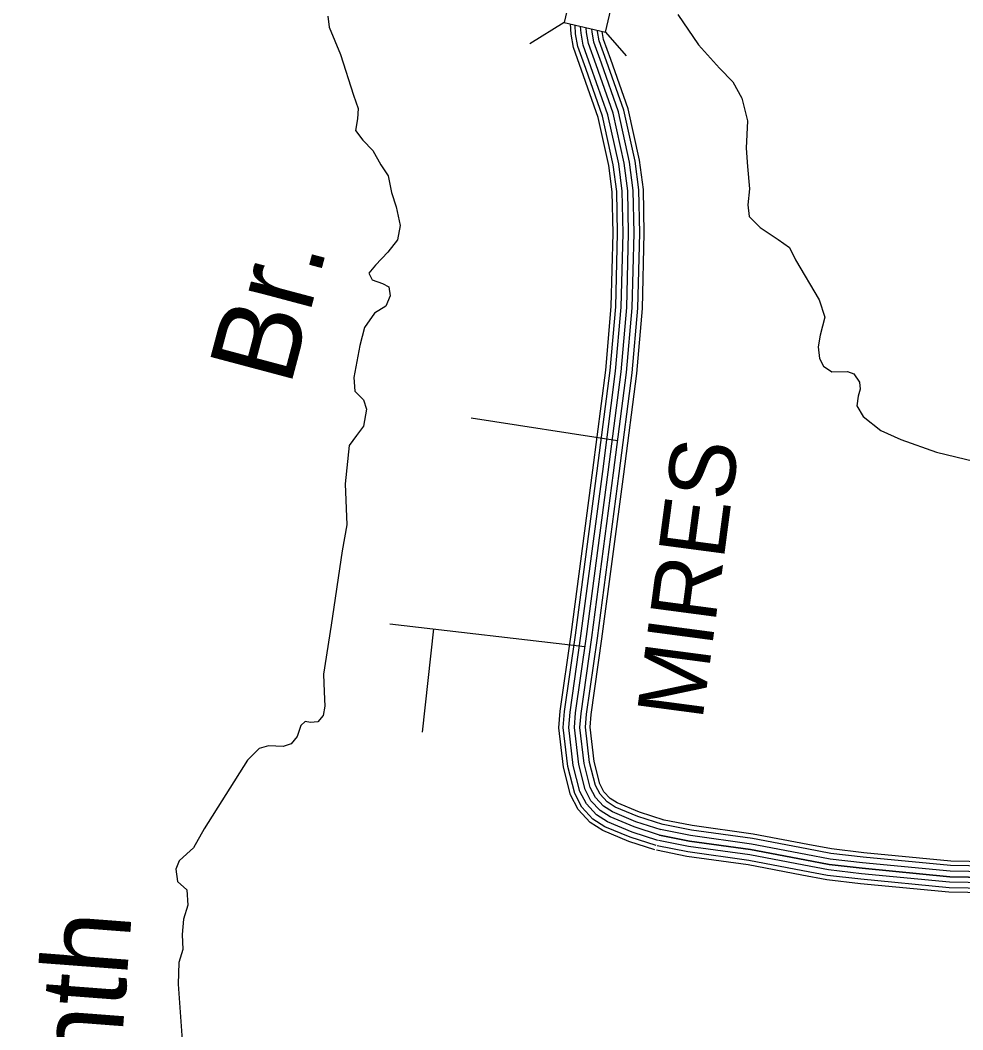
# Model space of a CAD drawing. Extents: x 1788175 to 1969470, y 584502 to 738744.
# Drawn here: x 1823466 to 1828747, y 641514 to 647171 of the extents above; entities that cross this region are included whole.
import ezdxf

# ---------------------------------------------------------------- set-up
doc = ezdxf.new("R2010")
doc.units = 0
for name, color, linetype in [('DESIGN - DRAINAGE - Bridges and Cross Drains Size Text', 7, 'Continuous'), ('DESIGN - ROW - Right-of-Way and Easement Labels', 7, 'Continuous'), ('DESIGN - TRANSPORTATION - Text', 7, 'Continuous'), ('SURVEY - DRAINAGE - Storm Sewer', 7, 'Continuous'), ('SURVEY - TRANSPORTATION - Roads', 7, 'Continuous')]:
    doc.layers.add(name, color=color, linetype=linetype)

msp = doc.modelspace()

# ---------------------------------------------------------------- linework, layer by layer
at = {"layer": 'DESIGN - TRANSPORTATION - Text'}
for points in [[(1825190.2, 647193.3), (1825196.9, 647131.5), (1825260.8, 646978.4), (1825333.6, 646751.5), (1825360.5, 646675.9), (1825355.3, 646617.9), (1825344.1, 646553.7), (1825386.7, 646498.4), (1825441.4, 646441.1), (1825486.4, 646359.8), (1825527.1, 646298.4), (1825546.3, 646204.7), (1825573.2, 646125.1), (1825594.5, 646021.4), (1825579.6, 645941.2), (1825526.6, 645870.5), (1825457.6, 645797.6), (1825420.2, 645753.1), (1825438.7, 645715.4), (1825496.8, 645696.2), (1825531, 645676.7), (1825539.7, 645626.8), (1825514.4, 645568.5), (1825451, 645529.6), (1825396.1, 645448.9), (1825369.5, 645348.5), (1825335.8, 645168.1), (1825340.8, 645092.2), (1825389.3, 645042.9), (1825406, 644991.2), (1825389.2, 644897), (1825349.9, 644844.5), (1825308.7, 644787.9), (1825287.5, 644573.7), (1825296.4, 644343.9), (1825270.3, 644197.6), (1825207.7, 643780.9), (1825165.3, 643506.4), (1825168.5, 643408.5), (1825173.6, 643326.6), (1825164.3, 643274.5), (1825134.7, 643240.1), (1825092.9, 643235.5), (1825062.8, 643241.1), (1825039.2, 643218.7), (1825018, 643156.5), (1824984.6, 643116), (1824938.8, 643101.4), (1824856.9, 643104.3), (1824805.2, 643089.5), (1824740.1, 643024.7), (1824497.4, 642639.4), (1824436.8, 642532.6), (1824399.3, 642500.1), (1824357.8, 642461.6), (1824338.5, 642413.3), (1824347.3, 642345.4), (1824399.9, 642298.2), (1824405, 642212.3), (1824382, 642134), (1824373.1, 642047.9), (1824378.2, 641964), (1824355.1, 641891.7), (1824350.7, 641769.7), (1824379.7, 641378.3)], [(1827151.1, 647202.7), (1827267.1, 647032.3), (1827384.6, 646902), (1827459.5, 646825.1), (1827508.6, 646733.8), (1827540.2, 646606.3), (1827534.1, 646454.3), (1827541.4, 646350.4), (1827553, 646226.6), (1827542.2, 646136.5), (1827551, 646070.7), (1827611.7, 646009.5), (1827712.4, 645943), (1827776.9, 645897.9), (1827809.7, 645828.4), (1827942.4, 645604.3), (1827973.6, 645506.8), (1827948.9, 645406.5), (1827937.8, 645340.3), (1827944.6, 645274.5), (1827967.1, 645232.8), (1828013.4, 645201.4), (1828101.3, 645202.7), (1828137.4, 645189.2), (1828167.9, 645143.6), (1828172.4, 645103.7), (1828160.9, 645063.5), (1828153.6, 645009.5), (1828188.4, 644950), (1828287.2, 644871.4), (1828399.7, 644821), (1828600.3, 644749.8)], [(1828600.3, 644749.8), (1828916.8, 644674.2)]]:
    msp.add_lwpolyline(points, dxfattribs=at)
at = {"layer": 'SURVEY - DRAINAGE - Storm Sewer'}
for p, q in [((1826514, 647158.1), (1826320.9, 647038.6)), ((1826745.3, 647103.7), (1826861.4, 646970.5))]:
    msp.add_line(p, q, dxfattribs=at)
msp.add_lwpolyline([(1826745.3, 647103.7), (1826799.7, 647335), (1826568.5, 647389.4), (1826514, 647158.1)], close=True, dxfattribs=at)
at = {"layer": 'SURVEY - TRANSPORTATION - Roads'}
for points in [[(1827021.4, 642522.5), (1826875.6, 642569.6), (1826731.2, 642629.8), (1826658.8, 642675), (1826592.4, 642747.5), (1826549.8, 642830), (1826510.2, 642984.6), (1826483.9, 643206.6), (1826491.8, 643299.9), (1826552.5, 643728.6), (1826674.5, 644649.4), (1826746.9, 645210.3), (1826777.9, 645566.2), (1826788.5, 645977.5), (1826783.6, 646208.7), (1826764.7, 646355.9), (1826705.2, 646626), (1826611.8, 646891.1), (1826565.8, 647017.3), (1826552.8, 647091.9), (1826549.9, 647149.7)], [(1827029, 642546), (1826884.1, 642592.8), (1826742.6, 642651.8), (1826674.8, 642694.2), (1826612.8, 642761.8), (1826573, 642838.9), (1826534.6, 642989.1), (1826508.7, 643207), (1826516.3, 643297.1), (1826577, 643725.3), (1826699, 644646.2), (1826771.5, 645207.7), (1826802.6, 645564.8), (1826813.2, 645977.4), (1826808.2, 646210.5), (1826789.1, 646360.2), (1826729, 646632.8), (1826635, 646899.5), (1826589.8, 647023.7), (1826577.5, 647094.6), (1826574.9, 647143.8)], [(1827038.5, 642575.5), (1826894.9, 642621.9), (1826756.9, 642679.4), (1826694.8, 642718.2), (1826638.5, 642779.7), (1826602.2, 642850), (1826565.1, 642994.8), (1826539.9, 643207.6), (1826547.1, 643293.6), (1826607.7, 643721.1), (1826729.7, 644642.2), (1826802.3, 645204.3), (1826833.6, 645563), (1826844.2, 645977.4), (1826839.2, 646212.8), (1826819.6, 646365.5), (1826758.9, 646641.3), (1826664.2, 646909.9), (1826619.9, 647031.7), (1826608.3, 647098.1), (1826606.4, 647136.4)], [(1827048, 642605), (1826905.6, 642651), (1826771.1, 642707.1), (1826714.8, 642742.3), (1826664.1, 642797.5), (1826631.4, 642861.1), (1826595.6, 643000.5), (1826571, 643208.1), (1826578, 643290.2), (1826638.4, 643716.8), (1826760.5, 644638.2), (1826833.2, 645201), (1826864.5, 645561.3), (1826875.2, 645977.3), (1826870.2, 646215.1), (1826850.2, 646370.8), (1826788.7, 646649.8), (1826693.4, 646920.4), (1826650, 647039.7), (1826639.2, 647101.6), (1826637.8, 647129)], [(1827048, 642605), (1826905.6, 642651), (1826771.1, 642707.1), (1826714.8, 642742.3), (1826664.1, 642797.5), (1826631.4, 642861.1), (1826595.6, 643000.5), (1826571, 643208.1), (1826578, 643290.2), (1826638.4, 643716.8), (1826760.5, 644638.2), (1826833.2, 645201), (1826864.5, 645561.3), (1826875.2, 645977.3), (1826870.2, 646215.1), (1826850.2, 646370.8), (1826788.7, 646649.8), (1826693.4, 646920.4), (1826650, 647039.7), (1826639.2, 647101.6), (1826637.8, 647129)], [(1827057.6, 642634.5), (1826916.4, 642680.1), (1826785.4, 642734.7), (1826734.8, 642766.3), (1826689.8, 642815.4), (1826660.5, 642872.2), (1826626.2, 643006.2), (1826602.2, 643208.6), (1826608.8, 643286.7), (1826669.1, 643712.6), (1826791.2, 644634.2), (1826864, 645197.7), (1826895.5, 645559.6), (1826906.2, 645977.2), (1826901.1, 646217.4), (1826880.8, 646376.1), (1826818.6, 646658.3), (1826722.6, 646930.8), (1826680, 647047.8), (1826670, 647105), (1826669.2, 647121.6)], [(1827067.1, 642664), (1826927.1, 642709.2), (1826799.7, 642762.3), (1826754.8, 642790.4), (1826715.4, 642833.3), (1826689.7, 642883.3), (1826656.7, 643011.9), (1826633.3, 643209.1), (1826639.6, 643283.2), (1826699.8, 643708.4), (1826821.9, 644630.2), (1826894.8, 645194.3), (1826926.5, 645557.8), (1826937.2, 645977.1), (1826932.1, 646219.7), (1826911.3, 646381.4), (1826848.5, 646666.9), (1826751.8, 646941.3), (1826710.1, 647055.8), (1826700.9, 647108.5), (1826700.6, 647114.2)], [(1827075, 642688.4), (1826936.1, 642733.3), (1826811.5, 642785.3), (1826771.4, 642810.3), (1826736.7, 642848.2), (1826713.9, 642892.5), (1826682.1, 643016.6), (1826659.2, 643209.6), (1826665.2, 643280.3), (1826725.3, 643704.9), (1826847.4, 644626.8), (1826920.4, 645191.6), (1826952.1, 645556.4), (1826962.9, 645977.1), (1826957.8, 646221.7), (1826936.7, 646385.8), (1826873.2, 646673.9), (1826776, 646950), (1826735, 647062.5), (1826727.1, 647108)], [(1826812.8, 644813.8), (1825993.3, 644941.4)], [(1825537.6, 643788.6), (1826630.5, 643661.2)], [(1825781, 643760.3), (1825718.9, 643181.2)], [(1831873.7, 641823.1), (1831191.7, 641894.4), (1831067.9, 641913.6), (1831035.9, 641923.8), (1831007, 641939.4), (1830897.7, 642010.1), (1830796.9, 642062.1), (1830711.9, 642092.6), (1830406.4, 642191.3), (1829947.7, 642309.9), (1829633.1, 642368), (1829329.4, 642422.4), (1829252.3, 642427.7), (1829172.2, 642428.7), (1828988.6, 642428.1), (1828678.1, 642433.7), (1828189.2, 642480.5), (1828008.1, 642501.6), (1827874.2, 642527.3), (1827568.3, 642585.3), (1827226.5, 642632.5), (1827060.2, 642665.8)], [(1831876.4, 641848.7), (1831195, 641919.9), (1831073.8, 641938.7), (1831045.9, 641947.6), (1831020.1, 641961.5), (1830910.7, 642032.4), (1830807.2, 642085.7), (1830720.2, 642117), (1830413.6, 642216), (1829953.2, 642335), (1829637.7, 642393.3), (1829332.6, 642447.9), (1829253.3, 642453.4), (1829172.3, 642454.4), (1828988.8, 642453.8), (1828679.5, 642459.4), (1828192, 642506.1), (1828012.1, 642527), (1827879, 642552.5), (1827572.5, 642610.7), (1827230.8, 642657.9), (1827065.2, 642691)], [(1827048, 642605), (1827216.2, 642571.3), (1827558.3, 642524.1), (1827862.6, 642466.4), (1827998.7, 642440.3), (1828182.7, 642418.9), (1828674.6, 642371.7), (1828988.2, 642366.1), (1829171.9, 642366.7), (1829249.8, 642365.7), (1829321.8, 642360.8), (1829622, 642307), (1829934.3, 642249.3), (1830389.1, 642131.7), (1830691.9, 642034), (1830772.1, 642005.1), (1830866.6, 641956.4), (1830975.4, 641886), (1831011.6, 641866.5), (1831053.7, 641853.1), (1831183.7, 641832.9), (1831867.3, 641761.4)], [(1831867.3, 641761.4), (1831183.7, 641832.9), (1831053.7, 641853.1), (1831011.6, 641866.5), (1830975.4, 641886), (1830866.6, 641956.4), (1830772.1, 642005.1), (1830691.9, 642034), (1830389.1, 642131.7), (1829934.3, 642249.3), (1829622, 642307), (1829321.8, 642360.8), (1829249.8, 642365.7), (1829171.9, 642366.7), (1828988.2, 642366.1), (1828674.6, 642371.7), (1828182.7, 642418.9), (1827998.7, 642440.3), (1827862.6, 642466.4), (1827558.3, 642524.1), (1827216.2, 642571.3), (1827048, 642605)], [(1831870.5, 641792.3), (1831187.7, 641863.6), (1831060.8, 641883.3), (1831023.7, 641895.1), (1830991.2, 641912.7), (1830882.2, 641983.3), (1830784.5, 642033.6), (1830701.9, 642063.3), (1830397.7, 642161.5), (1829941, 642279.6), (1829627.5, 642337.5), (1829325.6, 642391.6), (1829251.1, 642396.7), (1829172, 642397.7), (1828988.4, 642397.1), (1828676.3, 642402.7), (1828186, 642449.7), (1828003.4, 642470.9), (1827868.4, 642496.8), (1827563.3, 642554.7), (1827221.4, 642601.9), (1827054.1, 642635.4)], [(1831860.8, 641699.8), (1831175.7, 641771.4), (1831039.4, 641792.5), (1830987.2, 641809.2), (1830943.8, 641832.6), (1830835.5, 641902.7), (1830747.3, 641948.1), (1830671.9, 641975.3), (1830371.8, 642072.1), (1829920.9, 642188.8), (1829610.9, 642246), (1829314.1, 642299.1), (1829247.3, 642303.8), (1829171.6, 642304.7), (1828987.7, 642304.1), (1828671.1, 642309.8), (1828176.2, 642357.2), (1827989.3, 642379), (1827851, 642405.5), (1827548.3, 642462.9), (1827205.9, 642510.2), (1827035.9, 642544.2)], [(1831864, 641730.6), (1831179.7, 641802.1), (1831046.5, 641822.8), (1830999.4, 641837.8), (1830959.6, 641859.3), (1830851.1, 641929.6), (1830759.7, 641976.6), (1830681.9, 642004.6), (1830380.4, 642101.9), (1829927.6, 642219), (1829616.4, 642276.5), (1829317.9, 642329.9), (1829248.5, 642334.8), (1829171.8, 642335.7), (1828987.9, 642335.1), (1828672.8, 642340.8), (1828179.4, 642388), (1827994, 642409.6), (1827856.8, 642435.9), (1827553.3, 642493.5), (1827211, 642540.7), (1827041.9, 642574.6)], [(1831858.3, 641675.2), (1831172.6, 641746.9), (1831033.7, 641768.4), (1830977.6, 641786.3), (1830931.2, 641811.3), (1830823.1, 641881.3), (1830737.5, 641925.4), (1830663.9, 641951.9), (1830364.9, 642048.4), (1829915.5, 642164.6), (1829606.5, 642221.6), (1829311.1, 642274.6), (1829246.3, 642279.1), (1829171.5, 642279.9), (1828987.5, 642279.4), (1828669.6, 642285.1), (1828173.6, 642332.6), (1827985.5, 642354.5), (1827846.3, 642381.2), (1827544.3, 642438.5), (1827201.7, 642485.8), (1827031, 642519.9)]]:
    msp.add_lwpolyline(points, dxfattribs=at)

# ---------------------------------------------------------------- texts
at = {"layer": 'DESIGN - DRAINAGE - Bridges and Cross Drains Size Text'}
for s, rotation, p in [('Br.', 75.1071, (1824978.5, 645112)), ('Corinth', 85.6533, (1823936, 640117.6))]:
    msp.add_text(s, height=475, rotation=rotation, dxfattribs=at).set_placement(p)
at = {"layer": 'DESIGN - ROW - Right-of-Way and Easement Labels'}
msp.add_text('MIRES', height=370, rotation=82.454, dxfattribs=at).set_placement((1827287.8, 643242.8))

doc.saveas('drawing.dxf')
